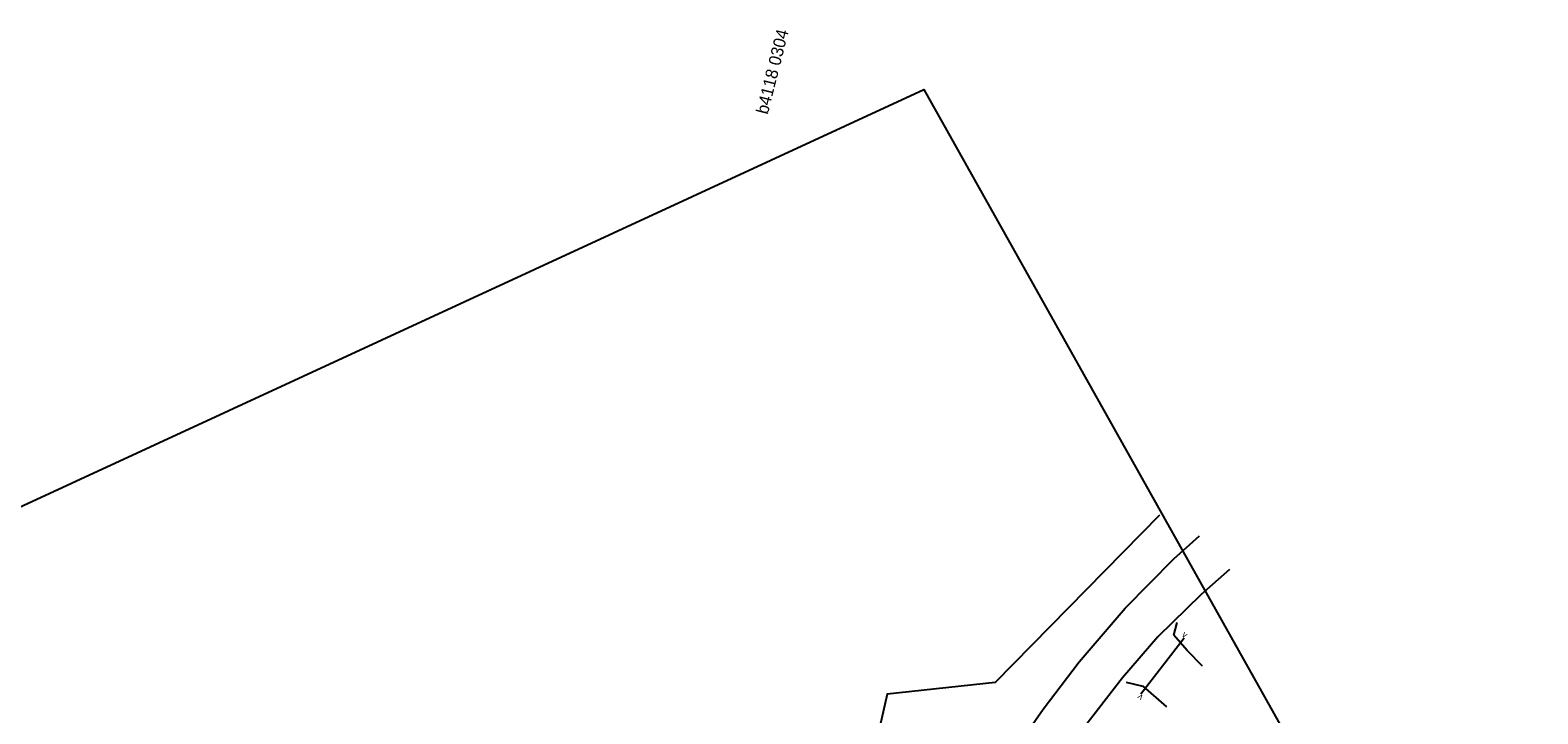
# Model space of a CAD drawing. Extents: x 1380524 to 1382335, y 594765 to 596944.
# Drawn here: x 1381533 to 1382148, y 596665 to 596944 of the extents above; entities that cross this region are included whole.
import ezdxf

# ---------------------------------------------------------------- set-up
doc = ezdxf.new("R2010")
doc.units = 0
for name, color, linetype in [('Prop Drainage Structure Box Number Symbol CELL', 7, 'Continuous'), ('Prop Drainage Structure Pipe CSP 15in', 7, 'Continuous'), ('Prop Drainage Structure Pipe Elbow CELL', 7, 'Continuous'), ('Prop Drainage Structure Pipe Elbow Label', 7, 'Continuous'), ('Prop Earthen Structure Cut Ditch Special Detail Label', 7, 'Continuous'), ('Prop Earthen Structure Ditch Flow Line', 7, 'Continuous')]:
    doc.layers.add(name, color=color, linetype=linetype)

msp = doc.modelspace()

# ---------------------------------------------------------------- linework, layer by layer
at = {"layer": 'Prop Drainage Structure Box Number Symbol CELL'}
msp.add_lwpolyline([(1382083.99, 595964.39), (1380966.64, 596251.47), (1381106.82, 596554.99), (1381897.61, 596920.15), (1382148.43, 596473.2)], close=True, dxfattribs=at)
at = {"layer": 'Prop Drainage Structure Pipe Elbow CELL'}
for points in [[(1382011.48, 596684.79), (1382005.18, 596691.07), (1381999.83, 596697.34), (1382001.14, 596702.59)], [(1381980.29, 596678.25), (1381987.1, 596676.55), (1381996.79, 596668.09)]]:
    msp.add_lwpolyline(points, dxfattribs=at)
at = {"layer": 'Prop Drainage Structure Pipe Elbow Label'}
msp.add_lwpolyline([(1381986.27, 596673.37), (1382004.01, 596696.24)], dxfattribs=at)
at = {"layer": 'Prop Earthen Structure Cut Ditch Special Detail Label'}
msp.add_lwpolyline([(1381993.97, 596746.39), (1381926.82, 596678.09), (1381882.73, 596673.31), (1381857.71, 596563.06), (1381849.31, 596464.5), (1381837.19, 596379.89), (1381830.78, 596342.77), (1381810.83, 596299.24), (1381745.1, 596224.39), (1381733.09, 596194.6), (1381689.78, 596209.04), (1381619.47, 596192.74), (1381567.86, 596179.57), (1381583.81, 596285.11), (1381565.74, 596343.12), (1381520.02, 596437.2), (1381483.63, 596516.56), (1381436.21, 596610.27), (1381402.81, 596651.16), (1381345.44, 596643.18), (1381336.65, 596668.79)], dxfattribs=at)
at = {"layer": 'Prop Earthen Structure Ditch Flow Line'}
for points in [[(1381933.85, 596649.2), (1381946.46, 596667.2), (1381961.13, 596686.48), (1381979.91, 596708.4), (1381999.73, 596728.6), (1382010.2, 596737.96)], [(1382022.53, 596724.24), (1382010.89, 596714.02), (1381993.29, 596696.66), (1381978.82, 596680.01), (1381960.19, 596655.9)]]:
    msp.add_lwpolyline(points, dxfattribs=at)

# ---------------------------------------------------------------- texts
at = {"layer": 'Prop Drainage Structure Pipe CSP 15in'}
msp.add_text('b4118 0304', height=5, rotation=75.93024, dxfattribs=at).set_placement((1381833.93, 596909.77))
at = {"layer": 'Prop Drainage Structure Pipe Elbow Label'}
for rotation, p in [(322.43759, (1382002.82, 596697.16)), (141.95589, (1381987.45, 596672.44))]:
    msp.add_text('v', height=2.65, rotation=rotation, dxfattribs=at).set_placement(p)

doc.saveas('drawing.dxf')
